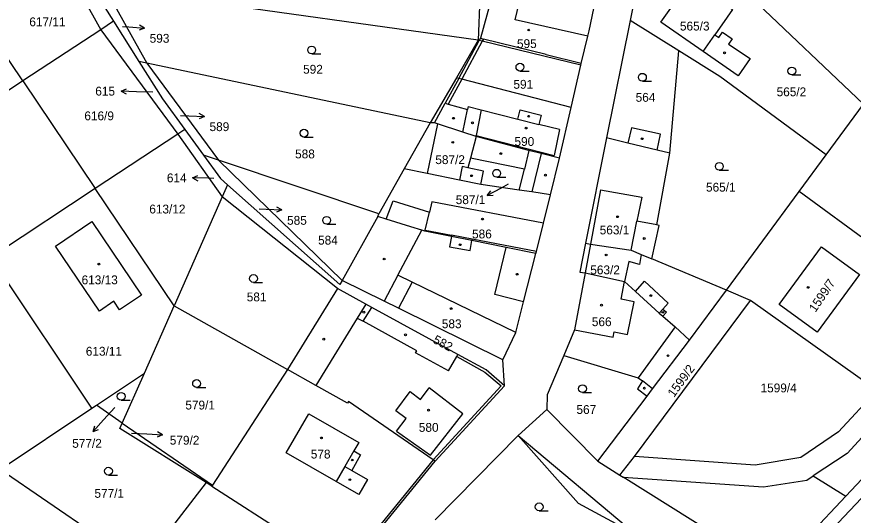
# Model space of a CAD drawing. Extents: x -724107 to -720612, y -1045267 to -1038441.
# Drawn here: x -722981 to -722820.2, y -1043041.7 to -1042945.9 of the extents above; entities that cross this region are included whole.
import ezdxf

# ---------------------------------------------------------------- set-up
doc = ezdxf.new("R2010")
doc.units = 0
for name, color, linetype in [('Hranice parcel', 7, 'Continuous'), ('Parcelní čísla', 7, 'Continuous'), ('Pop  PČ popisy', 7, 'Continuous'), ('Vnitřní kresba', 7, 'Continuous'), ('Značky budov', 7, 'Continuous'), ('Značky kultur', 7, 'Continuous')]:
    doc.layers.add(name, color=color, linetype=linetype)

msp = doc.modelspace()

# ---------------------------------------------------------------- linework, layer by layer
at = {"layer": 'Hranice parcel'}
for p, q in [((-722976.7, -1042927.12), (-722964.78, -1042948.38)), ((-722851.82, -1042930.69), (-722818.24, -1042962.72)), ((-722891.71, -1042936.65), (-722892.25, -1042950.4)), ((-722979.78, -1042958.24), (-722993.36, -1042938.06)), ((-722966.59, -1042940.01), (-722962.33, -1042946.77)), ((-722892.25, -1042950.4), (-722963.98, -1042940.37)), ((-722963.98, -1042940.37), (-722955.95, -1042954.81)), ((-722962.33, -1042946.77), (-722964.78, -1042948.38)), ((-722962.33, -1042946.77), (-722957.48, -1042954.49)), ((-722863.06, -1042946.59), (-722867.59, -1042969.18)), ((-722853.72, -1042952.42), (-722863.06, -1042946.59)), ((-722964.78, -1042948.38), (-722979.78, -1042958.24)), ((-722964.78, -1042948.38), (-722949.99, -1042968.48)), ((-722892.25, -1042950.4), (-722896.45, -1042957.62)), ((-722855.44, -1042972.13), (-722853.72, -1042952.42)), ((-722955.95, -1042954.81), (-722957.48, -1042954.49)), ((-722901.47, -1042966.26), (-722955.95, -1042954.81)), ((-722955.95, -1042954.81), (-722942.16, -1042973.45)), ((-722874.42, -1042963.36), (-722872.53, -1042955.21)), ((-722979.78, -1042958.24), (-722987.67, -1042963.43)), ((-722979.78, -1042958.24), (-722965.86, -1042978.93)), ((-722896.45, -1042957.62), (-722901.47, -1042966.26)), ((-722876.67, -1042973.09), (-722874.42, -1042963.36)), ((-722825.42, -1042972.46), (-722818.24, -1042962.72)), ((-722900.1, -1042966.5), (-722902.05, -1042976.04)), ((-722948.64, -1042967.59), (-722949.99, -1042968.48)), ((-722948.64, -1042967.59), (-722945.09, -1042972.47)), ((-722949.99, -1042968.48), (-722965.86, -1042978.93)), ((-722949.99, -1042968.48), (-722941.46, -1042980.49)), ((-722867.59, -1042969.18), (-722871.62, -1042989.43)), ((-722942.16, -1042973.45), (-722945.09, -1042972.47)), ((-722830.59, -1042979.47), (-722825.42, -1042972.46)), ((-722942.16, -1042973.45), (-722918.41, -1042996.61)), ((-722911.35, -1042983.8), (-722942.16, -1042973.45)), ((-722878.39, -1042980.09), (-722876.67, -1042973.09)), ((-722965.86, -1042978.93), (-722985.9, -1042992.13)), ((-722950.72, -1043001.44), (-722965.86, -1042978.93)), ((-722940.44, -1042978.19), (-722941.46, -1042980.49)), ((-722941.46, -1042980.49), (-722950.72, -1043001.44)), ((-722919.34, -1042998.14), (-722941.46, -1042980.49)), ((-722844.58, -1042998.46), (-722830.59, -1042979.47)), ((-722800.69, -1043001.47), (-722830.59, -1042979.47)), ((-722911.58, -1042984.31), (-722911.35, -1042983.8)), ((-722911.58, -1042984.31), (-722918.41, -1042996.61)), ((-722966.51, -1043021.13), (-722985.9, -1042992.13)), ((-722844.58, -1042998.46), (-722858.9, -1042992.42)), ((-722919.34, -1042998.14), (-722928.95, -1043013.7)), ((-722851.63, -1043008.03), (-722844.58, -1042998.46)), ((-722839.97, -1043000.4), (-722844.58, -1042998.46)), ((-722956.43, -1043014.42), (-722950.72, -1043001.44)), ((-722950.72, -1043001.44), (-722928.95, -1043013.7)), ((-722862.22, -1043030.39), (-722839.97, -1043000.4)), ((-722815.69, -1043017.71), (-722839.97, -1043000.4)), ((-722887.19, -1043016.8), (-722887.55, -1043011.8)), ((-722965.63, -1043020.55), (-722956.43, -1043014.42)), ((-722960.67, -1043023.97), (-722956.43, -1043014.42)), ((-722928.95, -1043013.7), (-722943.35, -1043035.93)), ((-722900.56, -1043031.3), (-722887.19, -1043016.8)), ((-722869.28, -1043031.33), (-722859.8, -1043018.82)), ((-722984.22, -1043032.91), (-722966.51, -1043021.13)), ((-722966.51, -1043021.13), (-722965.63, -1043020.55)), ((-722960.67, -1043023.97), (-722965.63, -1043020.55)), ((-722879.05, -1043021.4), (-722884.57, -1043026.38)), ((-722879.05, -1043021.4), (-722869.28, -1043031.33)), ((-722960.67, -1043023.97), (-722943.35, -1043035.93)), ((-722833.48, -1043054.07), (-722805, -1043023.99)), ((-722900.52, -1043042.56), (-722884.57, -1043026.38)), ((-722884.57, -1043026.38), (-722861.85, -1043045.43)), ((-722865.04, -1043033.98), (-722862.22, -1043030.39)), ((-722917.85, -1043052.52), (-722900.56, -1043031.3)), ((-722869.28, -1043031.33), (-722865.04, -1043033.98)), ((-722956.74, -1043051.61), (-722984.22, -1043032.91)), ((-722865.04, -1043033.98), (-722864.41, -1043034.39)), ((-722827.87, -1043034.11), (-722821.62, -1043038.02)), ((-722944.58, -1043035.41), (-722954.32, -1043048.05)), ((-722943.48, -1043036.12), (-722944.58, -1043035.41)), ((-722835.35, -1043052.56), (-722864.41, -1043034.39)), ((-722943.35, -1043035.93), (-722943.48, -1043036.12)), ((-722943.48, -1043036.12), (-722926.66, -1043046.88)), ((-722821.62, -1043038.02), (-722835.35, -1043052.56))]:
    msp.add_line(p, q, dxfattribs=at)
for points in [[(-722861.62, -1042927.28), (-722860.7, -1042934.82), (-722863.06, -1042946.59)], [(-722872.53, -1042955.21), (-722872.45, -1042954.88), (-722871.2, -1042949.65), (-722870.95, -1042948.59), (-722869.39, -1042941.19), (-722869.29, -1042935.24), (-722869.24, -1042932)], [(-722760.98, -1042943.24), (-722755.42, -1042937.45), (-722753.99, -1042938.85), (-722748.91, -1042933.56), (-722739.35, -1042942.87), (-722744.9, -1042948.66), (-722773.74, -1042978.75), (-722802.14, -1043008.85), (-722821.39, -1043029.83), (-722827.87, -1043034.11)], [(-722840.03, -1042953.93), (-722842.3, -1042957.22), (-722849.02, -1042952.58), (-722857.19, -1042946.94), (-722852.5, -1042940.35), (-722849.56, -1042942.38), (-722848.75, -1042941.18), (-722846.29, -1042942.89), (-722846.1, -1042942.62), (-722843.39, -1042944.51), (-722844.42, -1042945.98), (-722846.79, -1042949.38), (-722846.02, -1042949.9), (-722845.33, -1042948.88), (-722843.49, -1042950.12), (-722844.17, -1042951.14), (-722840.03, -1042953.93)], [(-722734.91, -1042943.57), (-722785.61, -1042999.98), (-722807.38, -1043022.94), (-722821.62, -1043038.02)], [(-722872.53, -1042955.21), (-722891.49, -1042950.59), (-722892.07, -1042950.44), (-722892.25, -1042950.4)], [(-722825.42, -1042972.46), (-722845.81, -1042957.36), (-722853.72, -1042952.42)], [(-722957.48, -1042954.49), (-722952.97, -1042961.65), (-722948.64, -1042967.59)], [(-722874.42, -1042963.36), (-722895.44, -1042957.88), (-722896.02, -1042957.73), (-722896.45, -1042957.62)], [(-722900.1, -1042966.5), (-722900.68, -1042966.31), (-722901.47, -1042966.26)], [(-722876.67, -1042973.09), (-722880.15, -1042972.18), (-722882.53, -1042971.57), (-722892.69, -1042968.92), (-722895.21, -1042968.1), (-722900.1, -1042966.5)], [(-722855.44, -1042972.13), (-722857.87, -1042971.54), (-722857.22, -1042968.45), (-722862.81, -1042967.27), (-722863.53, -1042970.17), (-722867.59, -1042969.18)], [(-722945.09, -1042972.47), (-722941.81, -1042976.97), (-722940.44, -1042978.19)], [(-722858.9, -1042992.42), (-722857.5, -1042985.98), (-722857.93, -1042985.9), (-722855.44, -1042972.13)], [(-722884.38, -1042979.22), (-722883.4, -1042975.17), (-722893.78, -1042973.08), (-722894.26, -1042974.91)], [(-722902.05, -1042976.04), (-722906.47, -1042975.13), (-722911.35, -1042983.8)], [(-722894.26, -1042974.91), (-722895.33, -1042974.67), (-722895.84, -1042977.31), (-722902.05, -1042976.04)], [(-722884.38, -1042979.22), (-722891.75, -1042978.15), (-722891.25, -1042975.57), (-722894.26, -1042974.91)], [(-722918.41, -1042996.61), (-722918.88, -1042997.38), (-722940.44, -1042978.19)], [(-722878.39, -1042980.09), (-722881.95, -1042979.57), (-722884.38, -1042979.22)], [(-722881.18, -1042991.4), (-722881.08, -1042991.01), (-722879.7, -1042985.57), (-722878.39, -1042980.09)], [(-722965.03, -1043002.5), (-722973.5, -1042989.97), (-722966.54, -1042985.27), (-722957, -1042999.4), (-722961.22, -1043002.21), (-722962.27, -1043000.58), (-722965.03, -1043002.5)], [(-722881.18, -1042991.4), (-722886.92, -1042990.24), (-722893.48, -1042988.91), (-722897.41, -1042988.11), (-722902.51, -1042987.08), (-722903.08, -1042986.91), (-722905.22, -1042986.26), (-722909.94, -1042984.81), (-722911.58, -1042984.31)], [(-722871.62, -1042989.43), (-722872.73, -1042995.01), (-722871.72, -1042995.14)], [(-722871.62, -1042989.43), (-722870.69, -1042989.57), (-722862.89, -1042990.74), (-722860.94, -1042991.56), (-722858.9, -1042992.42)], [(-722827.14, -1043006.52), (-722834.41, -1043001.18), (-722826.28, -1042990.09), (-722819.02, -1042995.41), (-722827.14, -1043006.52)], [(-722887.55, -1043011.8), (-722885.02, -1043006.58), (-722883.55, -1043000.71), (-722881.18, -1042991.4)], [(-722871.72, -1042995.14), (-722873.75, -1043006.04), (-722875.82, -1043010.99)], [(-722871.72, -1042995.14), (-722864.13, -1042996.78), (-722862.03, -1042998.67), (-722857.47, -1043002.84), (-722856.79, -1043003.43), (-722854.44, -1043005.5), (-722851.63, -1043008.03)], [(-722887.55, -1043011.8), (-722907.6, -1043001.91), (-722910.37, -1043000.55), (-722918.41, -1042996.61)], [(-722887.19, -1043016.8), (-722890.75, -1043013.77), (-722896.16, -1043010.81), (-722912.69, -1043001.78), (-722913.84, -1043001.15), (-722919.34, -1042998.14)], [(-722859.8, -1043018.82), (-722858.75, -1043017.42), (-722851.63, -1043008.03)], [(-722875.82, -1043010.99), (-722878.99, -1043018.58), (-722879.05, -1043021.4)], [(-722875.82, -1043010.99), (-722861.51, -1043015.28), (-722860.72, -1043015.89), (-722861.67, -1043017.4), (-722859.8, -1043018.82)], [(-722900.56, -1043031.3), (-722900.93, -1043031.04), (-722917.2, -1043019.85), (-722917.36, -1043020.13), (-722923.48, -1043016.73), (-722928.95, -1043013.7)], [(-722815.69, -1043017.71), (-722823.02, -1043025.69), (-722830.24, -1043030.6), (-722839.07, -1043032.1), (-722862.22, -1043030.39)], [(-722944.58, -1043035.41), (-722961.15, -1043025.05), (-722960.67, -1043023.97)], [(-722864.41, -1043034.39), (-722837.44, -1043036.25), (-722829.1, -1043034.93), (-722827.87, -1043034.11)]]:
    msp.add_lwpolyline(points, dxfattribs=at)
at = {"layer": 'Pop  PČ popisy'}
for p, q in [((-722960.63, -1042947.78), (-722959.4, -1042947.86)), ((-722959.4, -1042947.86), (-722956.41, -1042948.07)), ((-722956.41, -1042948.07), (-722957.44, -1042948.5)), ((-722956.41, -1042948.07), (-722957.37, -1042947.5)), ((-722960.91, -1042960.2), (-722959.89, -1042959.73)), ((-722957.91, -1042960.3), (-722960.91, -1042960.2)), ((-722960.91, -1042960.2), (-722959.93, -1042960.73)), ((-722954.77, -1042960.41), (-722957.91, -1042960.3)), ((-722949.48, -1042964.88), (-722947.9, -1042964.94)), ((-722947.9, -1042964.94), (-722944.9, -1042965.05)), ((-722944.9, -1042965.05), (-722945.88, -1042964.51)), ((-722944.9, -1042965.05), (-722945.92, -1042965.51)), ((-722947.15, -1042976.88), (-722946.14, -1042976.39)), ((-722944.15, -1042976.93), (-722947.15, -1042976.88)), ((-722947.15, -1042976.88), (-722946.16, -1042977.4)), ((-722943.06, -1042976.96), (-722944.15, -1042976.93)), ((-722887.87, -1042978.82), (-722890.52, -1042980.23)), ((-722890.52, -1042980.23), (-722889.87, -1042979.32)), ((-722886.49, -1042978.07), (-722887.87, -1042978.82)), ((-722890.52, -1042980.23), (-722889.4, -1042980.2)), ((-722929.99, -1042983.03), (-722930.97, -1042982.47)), ((-722934.34, -1042982.8), (-722932.99, -1042982.87)), ((-722932.99, -1042982.87), (-722929.99, -1042983.03)), ((-722929.99, -1042983.03), (-722931.02, -1042983.47)), ((-722962.1, -1043020.97), (-722964.26, -1043023.38)), ((-722964.26, -1043023.38), (-722966.27, -1043025.61)), ((-722966.27, -1043025.61), (-722965.97, -1043024.53)), ((-722966.27, -1043025.61), (-722965.23, -1043025.2)), ((-722958.89, -1043025.89), (-722955.94, -1043026.05)), ((-722955.94, -1043026.05), (-722952.94, -1043026.21)), ((-722952.94, -1043026.21), (-722953.92, -1043025.66)), ((-722952.94, -1043026.21), (-722953.97, -1043026.66))]:
    msp.add_line(p, q, dxfattribs=at)
at = {"layer": 'Vnitřní kresba'}
for p, q in [((-722871.2, -1042949.65), (-722885.16, -1042946.51)), ((-722896.02, -1042957.73), (-722892.07, -1042950.44)), ((-722891.85, -1042950.04), (-722892.07, -1042950.44)), ((-722891.85, -1042950.04), (-722891.27, -1042950.18)), ((-722891.27, -1042950.18), (-722891.49, -1042950.59)), ((-722879.19, -1042953.13), (-722891.27, -1042950.18)), ((-722849.02, -1042952.58), (-722846.79, -1042949.38)), ((-722891.49, -1042950.59), (-722895.44, -1042957.88)), ((-722879.21, -1042953.23), (-722879.19, -1042953.13)), ((-722872.45, -1042954.88), (-722879.21, -1042953.23)), ((-722896.02, -1042957.73), (-722898.63, -1042962.53)), ((-722895.44, -1042957.88), (-722898.05, -1042962.69)), ((-722900.68, -1042966.31), (-722898.63, -1042962.53)), ((-722898.63, -1042962.53), (-722898.05, -1042962.69)), ((-722898.05, -1042962.69), (-722894.34, -1042963.71)), ((-722894.22, -1042963.13), (-722894.34, -1042963.71)), ((-722894.22, -1042963.13), (-722891.68, -1042963.77)), ((-722895.21, -1042968.1), (-722894.34, -1042963.71)), ((-722891.68, -1042963.77), (-722892.65, -1042968.72)), ((-722891.68, -1042963.77), (-722884.64, -1042965.55)), ((-722884.64, -1042965.55), (-722884.19, -1042963.79)), ((-722884.19, -1042963.79), (-722880.19, -1042964.83)), ((-722880.19, -1042964.83), (-722880.63, -1042966.57)), ((-722901.47, -1042966.26), (-722906.47, -1042975.13)), ((-722884.64, -1042965.55), (-722880.63, -1042966.57)), ((-722876.62, -1042967.58), (-722880.63, -1042966.57)), ((-722876.62, -1042967.58), (-722877.67, -1042972.54)), ((-722892.69, -1042968.92), (-722893.78, -1042973.08)), ((-722892.69, -1042968.92), (-722892.65, -1042968.72)), ((-722892.65, -1042968.72), (-722877.67, -1042972.54)), ((-722857.87, -1042971.54), (-722863.53, -1042970.17)), ((-722882.53, -1042971.57), (-722883.4, -1042975.17)), ((-722880.15, -1042972.18), (-722881.95, -1042979.57)), ((-722891.75, -1042978.15), (-722895.84, -1042977.31)), ((-722868.76, -1042979.15), (-722870.69, -1042989.57)), ((-722868.76, -1042979.15), (-722860.81, -1042980.55)), ((-722860.81, -1042980.55), (-722861.76, -1042985.2)), ((-722909.94, -1042984.81), (-722908.61, -1042981.25)), ((-722908.61, -1042981.25), (-722901.65, -1042983.46)), ((-722901.17, -1042981.47), (-722901.65, -1042983.46)), ((-722879.7, -1042985.57), (-722901.17, -1042981.47)), ((-722902.48, -1042986.93), (-722901.65, -1042983.46)), ((-722862.89, -1042990.74), (-722861.76, -1042985.2)), ((-722857.93, -1042985.9), (-722861.76, -1042985.2)), ((-722907.7, -1042995.54), (-722903.08, -1042986.91)), ((-722902.48, -1042986.93), (-722902.51, -1042987.08)), ((-722902.48, -1042986.93), (-722897.37, -1042987.9)), ((-722897.41, -1042988.11), (-722897.79, -1042990.08)), ((-722897.37, -1042987.9), (-722897.41, -1042988.11)), ((-722893.43, -1042988.65), (-722897.37, -1042987.9)), ((-722893.84, -1042990.83), (-722893.48, -1042988.91)), ((-722893.43, -1042988.65), (-722893.48, -1042988.91)), ((-722881.08, -1042991.01), (-722893.43, -1042988.65)), ((-722897.79, -1042990.08), (-722893.84, -1042990.83)), ((-722889.1, -1042999.27), (-722886.92, -1042990.24)), ((-722870.69, -1042989.57), (-722871.72, -1042995.14)), ((-722860.94, -1042991.56), (-722861.3, -1042993.51)), ((-722863.34, -1042992.94), (-722864.13, -1042996.78)), ((-722861.3, -1042993.51), (-722863.34, -1042992.94)), ((-722907.7, -1042995.54), (-722910.37, -1043000.55)), ((-722904.95, -1042996.88), (-722907.7, -1042995.54)), ((-722904.95, -1042996.88), (-722907.6, -1043001.91)), ((-722885.02, -1043006.58), (-722904.95, -1042996.88)), ((-722864.82, -1043000.19), (-722864.13, -1042996.78)), ((-722862.03, -1042998.67), (-722860.3, -1042996.73)), ((-722860.3, -1042996.73), (-722855.78, -1043000.96)), ((-722883.55, -1043000.71), (-722889.1, -1042999.27)), ((-722862.28, -1043000.71), (-722864.82, -1043000.19)), ((-722913.84, -1043001.15), (-722915.5, -1043003.82)), ((-722914.4, -1043004.42), (-722912.69, -1043001.78)), ((-722863.56, -1043006.99), (-722862.28, -1043000.71)), ((-722855.78, -1043000.96), (-722856.77, -1043002.06)), ((-722857.47, -1043002.84), (-722856.77, -1043002.06)), ((-722856.1, -1043002.64), (-722856.79, -1043003.43)), ((-722856.77, -1043002.06), (-722856.1, -1043002.64)), ((-722915.5, -1043003.82), (-722923.48, -1043016.73)), ((-722915.5, -1043003.82), (-722914.4, -1043004.42)), ((-722904.05, -1043010.07), (-722914.4, -1043004.42)), ((-722873.75, -1043006.04), (-722866.31, -1043007.46)), ((-722866.31, -1043007.46), (-722866.11, -1043006.47)), ((-722866.11, -1043006.47), (-722863.56, -1043006.99)), ((-722854.44, -1043005.5), (-722861.51, -1043015.28)), ((-722904.29, -1043010.5), (-722904.05, -1043010.07)), ((-722897.99, -1043013.94), (-722904.29, -1043010.5)), ((-722897.99, -1043013.94), (-722896.39, -1043011.2)), ((-722896.39, -1043011.2), (-722896.16, -1043010.81)), ((-722896.39, -1043011.2), (-722890.97, -1043014.17)), ((-722890.97, -1043014.17), (-722887.84, -1043016.84)), ((-722858.75, -1043017.42), (-722860.72, -1043015.89)), ((-722908.11, -1043021.62), (-722905.35, -1043017.93)), ((-722905.35, -1043017.93), (-722903.35, -1043019.42)), ((-722903.35, -1043019.42), (-722901.72, -1043017.24)), ((-722895.24, -1043022.21), (-722901.72, -1043017.24)), ((-722887.84, -1043016.84), (-722900.93, -1043031.04)), ((-722929.17, -1043029.7), (-722924.83, -1043022.18)), ((-722924.83, -1043022.18), (-722915.22, -1043027.72)), ((-722906.14, -1043023.1), (-722908.11, -1043021.62)), ((-722901.41, -1043030.18), (-722895.24, -1043022.21)), ((-722907.97, -1043025.55), (-722906.14, -1043023.1)), ((-722907.97, -1043025.55), (-722901.41, -1043030.18)), ((-722873, -1043039.43), (-722884.57, -1043026.38)), ((-722915.22, -1043027.72), (-722916.15, -1043029.34)), ((-722919.55, -1043035.22), (-722929.17, -1043029.7)), ((-722916.15, -1043029.34), (-722917.89, -1043032.34)), ((-722914.88, -1043030.07), (-722916.58, -1043033.1)), ((-722916.15, -1043029.34), (-722914.88, -1043030.07)), ((-722917.89, -1043032.34), (-722919.55, -1043035.22)), ((-722900.93, -1043031.04), (-722918.23, -1043052.28)), ((-722917.89, -1043032.34), (-722916.58, -1043033.1)), ((-722916.58, -1043033.1), (-722913.53, -1043034.84)), ((-722915.19, -1043037.72), (-722919.55, -1043035.22)), ((-722913.53, -1043034.84), (-722915.19, -1043037.72)), ((-722861.85, -1043045.43), (-722873, -1043039.43))]:
    msp.add_line(p, q, dxfattribs=at)
msp.add_lwpolyline([(-722885.16, -1042946.51), (-722883.98, -1042941.62), (-722889.18, -1042940.42), (-722891.85, -1042950.04)], dxfattribs=at)
at = {"layer": 'Značky budov'}
for centre in [(-722882.57, -1042948.44), (-722844.92, -1042952.83), (-722882.57, -1042965.02), (-722897.03, -1042965.4), (-722893.39, -1042966.28), (-722883.04, -1042967.28), (-722860.77, -1042969.34), (-722897.17, -1042970.03), (-722887.93, -1042972.19), (-722879.36, -1042976.33), (-722893.53, -1042976.45), (-722865.48, -1042984.32), (-722891.45, -1042984.77), (-722860.35, -1042988.5), (-722895.73, -1042989.71), (-722910.33, -1042992.45), (-722867.68, -1042991.68), (-722965.17, -1042993.42), (-722884.78, -1042995.38), (-722828.86, -1042997.9), (-722859.08, -1042999.48), (-722897.46, -1043001.98), (-722868.58, -1043001.32), (-722914.25, -1043002.68), (-722856.79, -1043002.7), (-722921.96, -1043007.87), (-722906.23, -1043007.01), (-722855.79, -1043011.03), (-722860.34, -1043017.26), (-722901.8, -1043021.49), (-722922.4, -1043026.84), (-722916.46, -1043031.08), (-722916.92, -1043034.86)]:
    msp.add_circle(centre, 0.175, dxfattribs=at)
at = {"layer": 'Značky kultur'}
for p, q in [((-722924.27, -1042953.02), (-722922.52, -1042953.02)), ((-722884.25, -1042956.32), (-722882.5, -1042956.32)), ((-722860.71, -1042958.27), (-722858.96, -1042958.27)), ((-722832, -1042957.06), (-722830.25, -1042957.06)), ((-722925.76, -1042969.02), (-722924.01, -1042969.02)), ((-722845.94, -1042975.4), (-722844.19, -1042975.4)), ((-722888.71, -1042976.72), (-722886.96, -1042976.72)), ((-722921.39, -1042985.76), (-722919.64, -1042985.76)), ((-722935.45, -1042996.96), (-722933.7, -1042996.96)), ((-722946.39, -1043017.13), (-722944.64, -1043017.13)), ((-722960.89, -1043019.6), (-722959.14, -1043019.6)), ((-722872.22, -1043018.12), (-722870.47, -1043018.12)), ((-722963.33, -1043033.97), (-722961.58, -1043033.97)), ((-722880.55, -1043040.84), (-722878.8, -1043040.84))]:
    msp.add_line(p, q, dxfattribs=at)
for centre in [(-722924.27, -1042952.27), (-722884.25, -1042955.57), (-722860.71, -1042957.52), (-722832, -1042956.31), (-722925.76, -1042968.27), (-722845.94, -1042974.65), (-722888.71, -1042975.97), (-722921.39, -1042985.01), (-722935.45, -1042996.21), (-722946.39, -1043016.38), (-722872.22, -1043017.37), (-722960.89, -1043018.85), (-722963.33, -1043033.22), (-722880.55, -1043040.09)]:
    msp.add_circle(centre, 0.75, dxfattribs=at)

# ---------------------------------------------------------------- texts
at = {"layer": 'Parcelní čísla'}
for s, p in [('617/11', (-722978.54, -1042947.72)), ('565/3', (-722853.5, -1042948.54)), ('593', (-722955.41, -1042950.89)), ('595', (-722884.82, -1042951.91)), ('592', (-722925.92, -1042956.84)), ('591', (-722885.5, -1042959.73)), ('615', (-722965.86, -1042961.04)), ('565/2', (-722834.92, -1042961.17)), ('564', (-722862.01, -1042962.23)), ('616/9', (-722967.96, -1042965.79)), ('589', (-722943.9, -1042967.87)), ('590', (-722885.29, -1042970.72)), ('588', (-722927.46, -1042973.11)), ('587/2', (-722900.51, -1042974.21)), ('614', (-722952.1, -1042977.71)), ('565/1', (-722848.49, -1042979.5)), ('587/1', (-722896.59, -1042981.9)), ('613/12', (-722955.48, -1042983.7)), ('585', (-722929, -1042985.87)), ('586', (-722893.45, -1042988.49)), ('563/1', (-722868.92, -1042987.72)), ('584', (-722923.04, -1042989.68)), ('563/2', (-722870.73, -1042995.39)), ('613/13', (-722968.49, -1042997.31)), ('581', (-722936.75, -1043000.59)), ('583', (-722899.26, -1043005.75)), ('566', (-722870.43, -1043005.35)), ('613/11', (-722967.68, -1043011.03)), ('1599/4', (-722838.01, -1043018.08)), ('579/1', (-722948.55, -1043021.37)), ('567', (-722873.38, -1043022.23)), ('580', (-722903.68, -1043025.66)), ('577/2', (-722970.29, -1043028.73)), ('579/2', (-722951.54, -1043028.13)), ('578', (-722924.44, -1043030.79)), ('577/1', (-722966.02, -1043038.34))]:
    msp.add_text(s, height=1.7, dxfattribs=at).set_placement(p)
for s, rotation, p in [('1599/7', 56, (-722827.45, -1043002.81)), ('582', 332, (-722901.11, -1043008.48)), ('1599/2', 54, (-722854.64, -1043019.15))]:
    msp.add_text(s, height=1.7, rotation=rotation, dxfattribs=at).set_placement(p)

doc.saveas('drawing.dxf')
